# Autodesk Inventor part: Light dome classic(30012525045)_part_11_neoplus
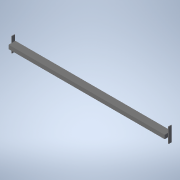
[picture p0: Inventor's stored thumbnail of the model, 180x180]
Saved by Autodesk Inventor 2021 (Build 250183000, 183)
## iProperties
Created: 2026-04
Part Number: Light dome classic(30012525045)_part_11_neoplus
Material: Generic
Catalog Web Link: www.3dfindit.com
Description: Light dome classic_part_11_neoplus-
Vendor: KINGSPAN
Document SubType Name: Modeling
Designer: psAdmin
Manufacturer: KINGSPAN
Mass: 1174.43 g
Surface Area: 1541.78 cm^2
Volume: 1174.43 cm^3
Density: 1 g/cm^3
Appearance: PSOLRGB-255-255-255
Category: PARTsolutions
Company: KINGSPAN
Title: Light dome classic(30012525045)_part_11_neoplus
Author: Cadenas PARTsolutions
PSOL_IDENT_0: {$CADENAS_DATA/23d-libs/kingspan_kla/light_dome_classic_neoplus/parts/part_11.prj},281 {VTYP=3D},{NB=
PSOL_IDENT_1: Light dome classic(30012525045)_part_11_neoplus},{LINA=Light dome classic(30012525045)_part_11_neopl
PSOL_IDENT_2: us},{NN=Light dome classic_part_11_neoplus},{DATE=15.07.2024 10:56:16},{GEOMDATE=01.07.2024 06:37:04
PSOL_IDENT_3: },{VERSION=},{LINEID=10},{WBVAR=LODLEVEL,L,W,DP,OP},{WBNUMERIC=W}  {NB=Light dome classic(3001252504
PSOL_IDENT_4: 5)_part_11_neoplus},{LINA=Light dome classic(30012525045)_part_11_neoplus},{KT=DUMMY},{IDNR=},{PN=Li
PSOL_IDENT_5: ght dome classic},{LODLEVEL=300},{L=125},{W=250},{DRIVE=1},{WX=125,250,300},{DP=4},{OP=5},{OPX='5','
PSOL_IDENT_6: Pneumatic - NRWG F.6 LK'},{LX=1250},{XWX=2500},{VER=2},{DPX='3', 'Fixed','1', 'Natural ventilation'
PSOL_IDENT_7: ,'4','NSHE', '2', 'NSHEV'}
NB: Light dome classic(30012525045)_part_11_neoplus
NN: Light dome classic_part_11_neoplus
NBSYN: $PN.($LODLEVEL.$L.$W.$DP.$OP.)_part_11_neoplus
LINA: Light dome classic(30012525045)_part_11_neoplus
CATALOG: Light + Air
PN: Light dome classic
LODLEVEL: 300
L: 125
W: 250
DP: NSHE
OP: Pneumatic - NRWG F.6 LK
SUPPLIER: KINGSPAN
ARTICLENO: Light dome classic(30012525045)_part_11_neoplus
BOMINFO: Light dome classic(30012525045)_part_11_neoplus
CREATOR: CADENAS GmbH
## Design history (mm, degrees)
sketch "Sketch_1"
  geometry: L1 (12.5, 33)-(-12.5, 33); L2 (-12.5, 33)-(-12.5, -12); L3 (-12.5, -12)-(12.5, -12); L4 (12.5, -12)-(12.5, 33)
  constraints: 8 end point
extrude "Extrusion1" join sketch "Sketch_1" stored distance "d0" = 1030; taper "d1" = 0 deg
sketch "Sketch_2"
  geometry: L1 (-36.5, 22)-(-36.5, 2); L2 (-36.5, 2)-(61.5, 2); L3 (61.5, 2)-(61.5, 22); L4 (61.5, 22)-(-36.5, 22)
  constraints: 8 end point
extrude "Extrusion2" join sketch "Sketch_2" distance "d2" = 4; taper "d3" = 0 deg
sketch "Sketch_3"
  geometry: L1 (-36.5, 22)-(-36.5, 2); L2 (-36.5, 2)-(61.5, 2); L3 (61.5, 2)-(61.5, 22); L4 (61.5, 22)-(-36.5, 22)
  constraints: 8 end point
extrude "Extrusion3" join sketch "Sketch_3" distance "d4" = 4; taper "d5" = 0 deg
node "IP_11_XY"
node "IP_11_YZ"
node "IP_11_ZX"
node "IP_11_X"
node "IP_11_Y"
node "IP_11_Z"
node "IP_11_Center"
body "Solid1"
